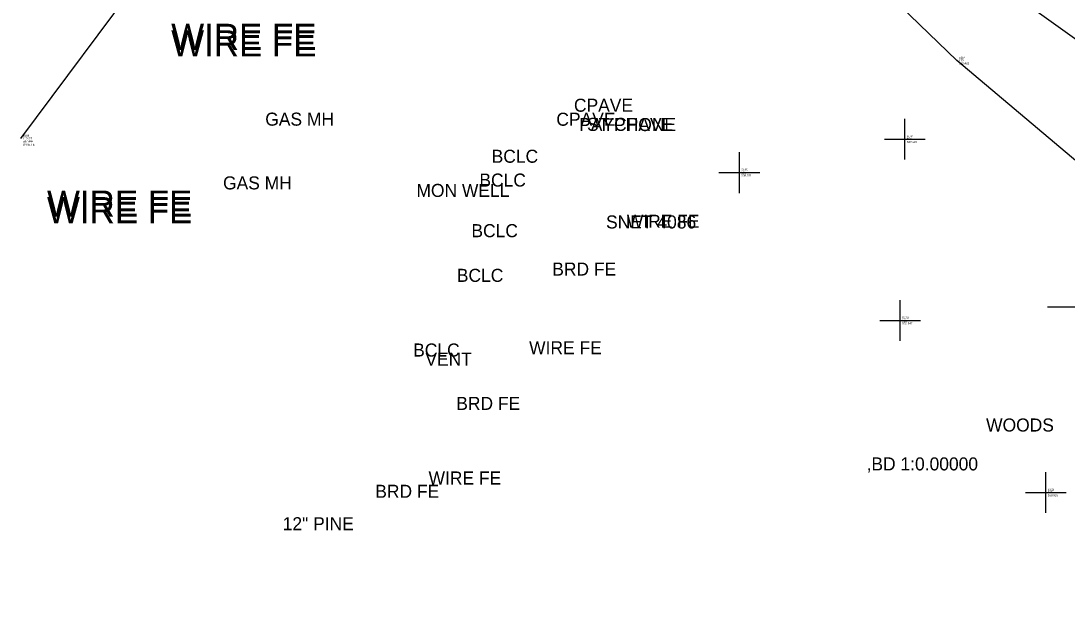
# Model space of a CAD drawing. Extents: x 5447 to 709667, y 4528 to 375505.
# Drawn here: x 706302.5 to 706430.8, y 374863.8 to 374934.5 of the extents above; entities that cross this region are included whole.
import ezdxf

# ---------------------------------------------------------------- set-up
doc = ezdxf.new("R2010")
doc.units = 0
for name, color, linetype in [('SV_BKLN_BKLN', 7, 'Continuous'), ('SV_FENC_FENCES', 7, 'Continuous'), ('SV_NODES_ACTIVE_POINT', 7, 'Continuous'), ('SV_NODES_DESCRIPTION', 7, 'Continuous'), ('SV_NODES_ELEVATION', 7, 'Continuous'), ('SV_NODES_PT_NUMBER', 7, 'Continuous'), ('SV_SURF_SPOT', 7, 'Continuous'), ('SV_SURVEY_NOTES', 7, 'Continuous')]:
    doc.layers.add(name, color=color, linetype=linetype)

msp = doc.modelspace()

# ---------------------------------------------------------------- linework, layer by layer
at = {"layer": 'SV_BKLN_BKLN'}
msp.add_lwpolyline([(706511.26, 374873.34), (706480.59, 374896.12), (706452.81, 374917.25), (706424.04, 374937.87), (706398.83, 374953.1)], dxfattribs=at)
at = {"layer": 'SV_FENC_FENCES'}
for points in [[(706302.47, 374920.06), (706317.71, 374940.52), (706332.49, 374959.2), (706344.83, 374975.18), (706356.82, 374990.69)], [(706554.86, 374828.93), (706534.54, 374841.87), (706513.2, 374854.66), (706486.45, 374872.63), (706460.96, 374892.31), (706434.27, 374915.35), (706417.33, 374929.63), (706387.43, 374958.47)]]:
    msp.add_lwpolyline(points, dxfattribs=at)
at = {"layer": 'SV_NODES_ACTIVE_POINT'}
for p, q in [((706417.33, 374929.63), (706417.33, 374929.63)), ((706302.47, 374920.06), (706302.47, 374920.06))]:
    msp.add_line(p, q, dxfattribs=at)
at = {"layer": 'SV_SURF_SPOT'}
for p, q in [((706410.94, 374917.48), (706410.94, 374922.48)), ((706408.44, 374919.98), (706413.44, 374919.98)), ((706410.94, 374919.98), (706410.94, 374919.98)), ((706390.63, 374913.36), (706390.63, 374918.36)), ((706388.13, 374915.86), (706393.13, 374915.86)), ((706390.63, 374915.86), (706390.63, 374915.86)), ((706410.37, 374895.22), (706410.37, 374900.22)), ((706428.46, 374899.41), (706433.46, 374899.41)), ((706407.87, 374897.72), (706412.87, 374897.72)), ((706410.37, 374897.72), (706410.37, 374897.72)), ((706428.23, 374874.12), (706428.23, 374879.12)), ((706425.73, 374876.62), (706430.73, 374876.62)), ((706428.23, 374876.62), (706428.23, 374876.62))]:
    msp.add_line(p, q, dxfattribs=at)

# ---------------------------------------------------------------- texts
at = {"layer": 'SV_NODES_DESCRIPTION'}
for s, p in [('113', (706417.58, 374929.5)), ('113 ST', (706302.72, 374919.93)), ('515', (706411.19, 374919.85)), ('515', (706390.88, 374915.74)), ('515', (706410.62, 374897.59)), ('515', (706428.48, 374876.5))]:
    msp.add_text(s, height=0.25, dxfattribs=at).set_placement(p)
at = {"layer": 'SV_NODES_ELEVATION'}
for s, p in [('539.482', (706417.58, 374929.15)), ('537.444', (706302.72, 374919.58)), ('538.997', (706411.19, 374919.5)), ('538.371', (706390.88, 374915.39)), ('539.847', (706410.62, 374897.24)), ('539.933', (706428.48, 374876.15))]:
    msp.add_text(s, height=0.25, dxfattribs=at).set_placement(p)
at = {"layer": 'SV_NODES_PT_NUMBER'}
for s, p in [('5157', (706417.58, 374929.85)), ('1069', (706302.72, 374920.28)), ('5144', (706411.19, 374920.2)), ('5135', (706390.88, 374916.09)), ('5134', (706410.62, 374897.94)), ('5133', (706428.48, 374876.85))]:
    msp.add_text(s, height=0.25, dxfattribs=at).set_placement(p)
at = {"layer": 'SV_SURVEY_NOTES'}
for s, height, p in [('WIRE FE', 3.2, (706320.91, 374930.92)), ('WIRE FE', 3.2, (706320.91, 374930.92)), ('WIRE FE', 3.2, (706320.91, 374930.92)), ('WIRE FE', 3.2, (706320.91, 374930.92)), ('WIRE FE', 3.2, (706320.91, 374930.92)), ('WIRE FE', 3.2, (706320.91, 374930.92)), ('WIRE FE', 3.2, (706320.91, 374930.92)), ('WIRE FE', 3.2, (706320.91, 374930.92)), ('WIRE FE', 3.2, (706320.91, 374930.12)), ('WIRE FE', 3.2, (706320.91, 374930.12)), ('WIRE FE', 3.2, (706320.91, 374930.12)), ('CPAVE', 1.6, (706370.33, 374923.33)), ('GAS MH', 1.6, (706332.45, 374921.62)), ('CPAVE', 1.6, (706368.17, 374921.61)), ('PAYPHONE', 1.6, (706370.97, 374920.96)), ('ST CPAVE', 1.6, (706371.93, 374920.98)), ('WIRE FE', 0.25, (706302.72, 374919.18)), ('BCLC', 1.6, (706360.23, 374917.07)), ('GAS MH', 1.6, (706327.27, 374913.8)), ('BCLC', 1.6, (706358.73, 374914.15)), ('WIRE FE', 3.2, (706305.67, 374910.46)), ('WIRE FE', 3.2, (706305.67, 374910.46)), ('WIRE FE', 3.2, (706305.67, 374910.46)), ('WIRE FE', 3.2, (706305.67, 374910.46)), ('WIRE FE', 3.2, (706305.67, 374910.46)), ('WIRE FE', 3.2, (706305.67, 374910.46)), ('WIRE FE', 3.2, (706305.67, 374910.46)), ('WIRE FE', 3.2, (706305.67, 374910.46)), ('MON WELL', 1.6, (706351, 374912.88)), ('WIRE FE', 3.2, (706305.67, 374909.66)), ('WIRE FE', 3.2, (706305.67, 374909.66)), ('WIRE FE', 3.2, (706305.67, 374909.66)), ('SNET 4086', 1.6, (706374.27, 374909.01)), ('WIRE FE', 1.6, (706376.82, 374909.09)), ('BCLC', 1.6, (706357.75, 374907.94)), ('BRD FE', 1.6, (706367.67, 374903.23)), ('BCLC', 1.6, (706355.96, 374902.46)), ('BCLC', 1.6, (706350.6, 374893.3)), ('WIRE FE', 1.6, (706364.83, 374893.58)), ('VENT', 1.6, (706352.1, 374892.17)), ('BRD FE', 1.6, (706355.89, 374886.75)), ('WOODS', 1.6, (706420.91, 374884.1)), (',BD 1:0.00000', 1.6, (706406.24, 374879.33)), ('WIRE FE', 1.6, (706352.49, 374877.6)), ('BRD FE', 1.6, (706345.95, 374875.97)), ('12" PINE', 1.6, (706334.59, 374871.99))]:
    msp.add_text(s, height=height, dxfattribs=at).set_placement(p)

doc.saveas('drawing.dxf')
